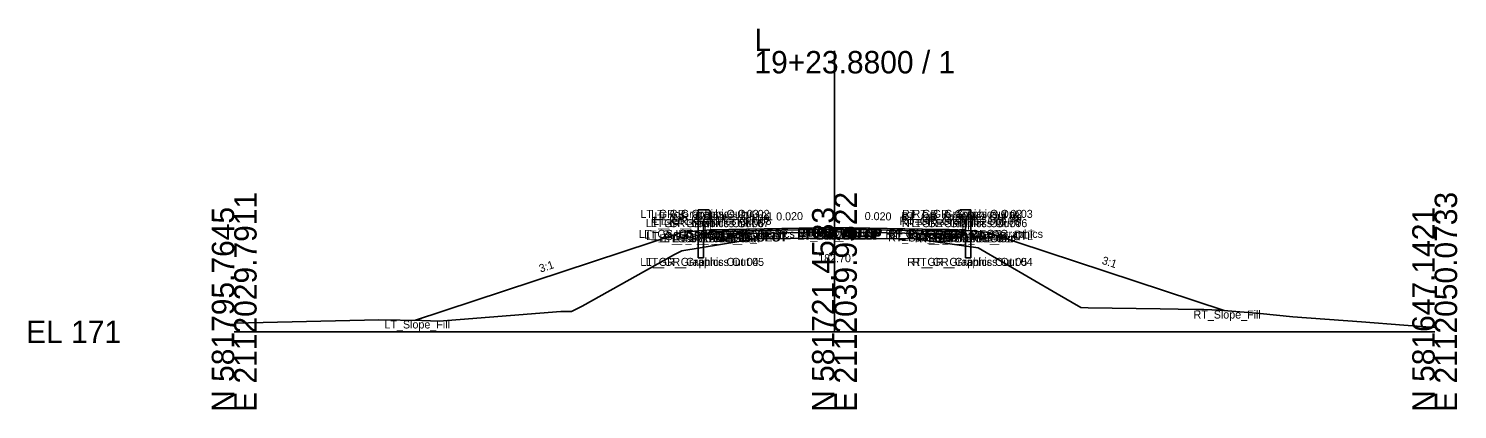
# Model space of a CAD drawing. Extents: x -26 to 3453, y -333 to 9539.
# Drawn here: x 3274.3 to 3452.8, y 990.3 to 1037.9 of the extents above; entities that cross this region are included whole.
import ezdxf

# ---------------------------------------------------------------- set-up
doc = ezdxf.new("R2010")
doc.units = 0
for name, color, linetype in [('Default', 7, 'Continuous'), ('Exist Cross Section Cell', 7, 'Continuous'), ('Exist XS Ground Line', 7, 'Continuous'), ('Prop CMT Guardrail Graphics', 7, 'Continuous'), ('Prop CMT Pvmt Course 1', 7, 'Continuous'), ('Prop CMT Pvmt Course 2', 7, 'Continuous'), ('Prop CMT Pvmt Course 3', 7, 'Continuous'), ('Prop CMT Pvmt Surface', 7, 'Continuous'), ('Prop CMT Pvmt Surface Shoulder', 7, 'Continuous'), ('Prop CMT Shld Paved Course 1', 7, 'Continuous'), ('Prop CMT Shld Paved Course 2', 7, 'Continuous'), ('Prop CMT Shld Paved Course 3', 7, 'Continuous'), ('Prop CMT Slope Grass', 7, 'Continuous'), ('Prop CMT Subgrade Earthwork', 7, 'Continuous'), ('Prop XS SE Text', 7, 'Continuous'), ('Prop XS Side Slope Text', 7, 'Continuous'), ('Scratch_Level_0', 7, 'Continuous')]:
    doc.layers.add(name, color=color, linetype=linetype)

msp = doc.modelspace()

# ---------------------------------------------------------------- linework, layer by layer
at = {"layer": 'Exist Cross Section Cell'}
for p, q in [((3375, 1000), (3375, 1035.09)), ((3300, 1000), (3375, 1000)), ((3375, 1000), (3450, 1000))]:
    msp.add_line(p, q, dxfattribs=at)
at = {"layer": 'Exist XS Ground Line'}
msp.add_lwpolyline([(3300, 1001.09), (3318.06, 1001.48), (3323.44, 1001.4), (3325.59, 1001.35), (3340.81, 1002.54), (3342.15, 1002.55), (3342.57, 1002.76), (3343.46, 1003.2), (3355.03, 1009.65), (3355.92, 1010.12), (3363.29, 1011.34), (3364.53, 1011.55), (3365.26, 1011.61), (3373.78, 1011.69), (3374.67, 1011.7), (3375, 1011.7), (3383.77, 1011.64), (3384.8, 1011.65), (3386.75, 1011.39), (3392.96, 1010.49), (3402.83, 1004.73), (3405.77, 1003.04), (3406.69, 1003.01), (3415.69, 1002.88), (3420.18, 1002.81), (3421.17, 1002.79), (3423.15, 1002.7), (3428.18, 1002.29), (3432.27, 1001.89), (3440.87, 1001.24), (3446.13, 1000.83), (3450, 1000.54)], dxfattribs=at)
at = {"layer": 'Prop CMT Guardrail Graphics'}
for points in [[(3357.97, 1009.24), (3357.97, 1015.24)], [(3357.97, 1015.24), (3359.3, 1015.24), (3359.57, 1014.95)], [(3359.57, 1014.37), (3359.3, 1014.08), (3358.64, 1014.08)], [(3358.64, 1014.08), (3358.64, 1009.24)], [(3359.57, 1014.95), (3359.3, 1014.66)], [(3359.3, 1014.66), (3359.57, 1014.37)], [(3392.03, 1015.24), (3390.7, 1015.24), (3390.43, 1014.95)], [(3390.43, 1014.95), (3390.7, 1014.66)], [(3390.7, 1014.66), (3390.43, 1014.37)], [(3390.43, 1014.37), (3390.7, 1014.08), (3391.36, 1014.08)], [(3391.36, 1014.08), (3391.36, 1009.24)], [(3392.03, 1009.24), (3392.03, 1015.24)], [(3358.64, 1009.24), (3357.97, 1009.24)], [(3391.36, 1009.24), (3392.03, 1009.24)]]:
    msp.add_lwpolyline(points, dxfattribs=at)
at = {"layer": 'Prop CMT Pvmt Course 1'}
for points in [[(3375, 1013.05), (3364, 1012.83)], [(3364, 1012.62), (3375, 1012.84)], [(3364, 1012.83), (3364, 1012.62)], [(3375, 1012.84), (3375, 1013.05)], [(3375, 1013.05), (3386, 1012.83)], [(3375, 1012.84), (3375, 1013.05)], [(3386, 1012.62), (3375, 1012.84)], [(3386, 1012.83), (3386, 1012.62)]]:
    msp.add_lwpolyline(points, dxfattribs=at)
msp.add_lwpolyline([(3375, 1012.84), (3375, 1012.93), (3375, 1012.93), (3375, 1012.84)], close=True, dxfattribs=at)
msp.add_lwpolyline([(3375, 1012.84), (3375, 1012.93), (3375, 1012.93), (3375, 1012.84)], close=True, dxfattribs=at)
at = {"layer": 'Prop CMT Pvmt Course 2'}
for points in [[(3375, 1012.84), (3364, 1012.62)], [(3364, 1012.62), (3364, 1012.29)], [(3364, 1012.29), (3375, 1012.51)], [(3375, 1012.51), (3375, 1012.84)], [(3375, 1012.51), (3375, 1012.84)], [(3375, 1012.84), (3386, 1012.62)], [(3386, 1012.29), (3375, 1012.51)], [(3386, 1012.62), (3386, 1012.29)]]:
    msp.add_lwpolyline(points, dxfattribs=at)
at = {"layer": 'Prop CMT Pvmt Course 3'}
for points in [[(3375, 1012.51), (3364, 1012.29)], [(3364, 1012.29), (3375, 1012.51)], [(3364, 1012.29), (3364, 1012.29)], [(3375, 1012.51), (3375, 1012.51)], [(3375, 1012.51), (3386, 1012.29)], [(3386, 1012.29), (3375, 1012.51)], [(3375, 1012.51), (3375, 1012.51)], [(3386, 1012.29), (3386, 1012.29)]]:
    msp.add_lwpolyline(points, dxfattribs=at)
at = {"layer": 'Prop CMT Pvmt Surface'}
for points in [[(3375, 1013.05), (3364, 1012.83)], [(3375, 1013.05), (3386, 1012.83)]]:
    msp.add_lwpolyline(points, dxfattribs=at)
at = {"layer": 'Prop CMT Pvmt Surface Shoulder'}
for points in [[(3364, 1012.83), (3359.58, 1012.74)], [(3386, 1012.83), (3390.42, 1012.74)]]:
    msp.add_lwpolyline(points, dxfattribs=at)
at = {"layer": 'Prop CMT Shld Paved Course 1'}
for points in [[(3364, 1012.83), (3359.58, 1012.74), (3359.37, 1012.53)], [(3359.37, 1012.53), (3364, 1012.62)], [(3364, 1012.62), (3364, 1012.83)], [(3386, 1012.83), (3390.42, 1012.74), (3390.63, 1012.53)], [(3386, 1012.62), (3386, 1012.83)], [(3390.63, 1012.53), (3386, 1012.62)]]:
    msp.add_lwpolyline(points, dxfattribs=at)
at = {"layer": 'Prop CMT Shld Paved Course 2'}
for points in [[(3364, 1012.62), (3359.37, 1012.53), (3359.03, 1012.19)], [(3359.03, 1012.19), (3364, 1012.29)], [(3364, 1012.29), (3364, 1012.62)], [(3386, 1012.62), (3390.63, 1012.53), (3390.97, 1012.19)], [(3386, 1012.29), (3386, 1012.62)], [(3390.97, 1012.19), (3386, 1012.29)]]:
    msp.add_lwpolyline(points, dxfattribs=at)
at = {"layer": 'Prop CMT Shld Paved Course 3'}
for points in [[(3364, 1012.29), (3359.03, 1012.19)], [(3359.03, 1012.19), (3364, 1012.29)], [(3364, 1012.29), (3364, 1012.29)], [(3386, 1012.29), (3390.97, 1012.19)], [(3390.97, 1012.19), (3386, 1012.29)], [(3386, 1012.29), (3386, 1012.29)], [(3359.03, 1012.19), (3359.03, 1012.19), (3359.03, 1012.19)], [(3390.97, 1012.19), (3390.97, 1012.19), (3390.97, 1012.19)]]:
    msp.add_lwpolyline(points, dxfattribs=at)
at = {"layer": 'Prop CMT Slope Grass'}
for points in [[(3356, 1012.46), (3322.54, 1001.42)], [(3359.57, 1012.74), (3356, 1012.46)], [(3359.58, 1012.74), (3359.57, 1012.74)], [(3390.42, 1012.74), (3390.43, 1012.74)], [(3390.43, 1012.74), (3394, 1012.46)], [(3394, 1012.46), (3423.7, 1002.66)]]:
    msp.add_lwpolyline(points, dxfattribs=at)
at = {"layer": 'Prop CMT Subgrade Earthwork'}
for points in [[(3359.03, 1012.19), (3358.56, 1012.66)], [(3364, 1012.29), (3359.03, 1012.19)], [(3375, 1012.51), (3364, 1012.29)], [(3375, 1012.51), (3386, 1012.29)], [(3386, 1012.29), (3390.97, 1012.19)], [(3390.97, 1012.19), (3391.44, 1012.66)]]:
    msp.add_lwpolyline(points, dxfattribs=at)

# ---------------------------------------------------------------- texts
at = {"layer": 'Default'}
msp.add_text('-', height=0.0001, dxfattribs=at).set_placement((3300, 1000))
at = {"layer": 'Exist Cross Section Cell'}
for s, p in [('L', (3365, 1035.09)), ('19+23.8800 / 1', (3365, 1032.29)), ('EL 171', (3274, 998.6))]:
    msp.add_text(s, height=2.8, dxfattribs=at).set_placement(p)
for s, p in [('E 2112029.7911', (3302.8, 990)), ('E 2112039.9322', (3377.8, 990)), ('E 2112050.0733', (3452.8, 990)), ('N 581795.7645', (3300, 990)), ('N 581721.4533', (3375, 990)), ('N 581647.1421', (3450, 990))]:
    msp.add_text(s, height=2.8, rotation=90, dxfattribs=at).set_placement(p)
at = {"layer": 'Exist XS Ground Line'}
msp.add_text('182.70', height=1, dxfattribs=at).set_placement((3372.97, 1008.7))
at = {"layer": 'Prop XS SE Text'}
for rotation, p in [(1.1458, (3367.73, 1013.91)), (358.8542, (3378.77, 1013.98))]:
    msp.add_text('0.020', height=1, rotation=rotation, dxfattribs=at).set_placement(p)
at = {"layer": 'Prop XS Side Slope Text'}
for rotation, p in [(18.2629, (3338.28, 1007.4)), (341.7371, (3408.33, 1008.52))]:
    msp.add_text('3:1', height=1, rotation=rotation, dxfattribs=at).set_placement(p)
at = {"layer": 'Scratch_Level_0'}
for s, p in [('LT_GR_Graphics Out 03', (3350.75, 1014.24)), ('LT_GR_Graphics Out 06', (3351.41, 1013.08)), ('LT_GR_Graphics Out 07', (3352.06, 1013.08)), ('LT_GR_Graphics Out 09', (3352.08, 1013.66)), ('LT_GR_Graphics Out 02', (3352.1, 1014.24)), ('LT_GR_Graphics Out 08', (3352.34, 1013.37)), ('LT_GR_Graphics Out 01', (3352.52, 1013.95)), ('RT_GR_Graphics Out 08', (3383.14, 1013.37)), ('RT_GR_Graphics Out 01', (3383.31, 1013.95)), ('RT_GR_Graphics Out 07', (3383.4, 1013.08)), ('RT_GR_Graphics Out 09', (3383.41, 1013.66)), ('RT_GR_Graphics Out 02', (3383.44, 1014.24)), ('RT_GR_Graphics Out 06', (3384.08, 1013.08)), ('RT_GR_Graphics Out 03', (3384.76, 1014.24)), ('LT_GS_OS_GR_Face_Graphics', (3350.57, 1011.74)), ('LT_Sub_Trench_Out_DLT', (3351.21, 1011.66)), ('LT_GS_OS_CTL', (3351.46, 1011.46)), ('LT_PS2_OEOP', (3355.16, 1011.53)), ('LT_PS1_OEOP', (3355.49, 1011.74)), ('LT_PV2_OEOT', (3359.75, 1011.62)), ('LT_PV3_OEOT', (3359.75, 1011.29)), ('LT_Sub_OEOT', (3359.77, 1011.29)), ('LT_PV1_OEOT', (3359.87, 1011.83)), ('RT_PV2_OEEOP', (3370.33, 1011.84)), ('RT_PV3_OEEOP', (3370.33, 1011.51)), ('RT_Sub_OEEOP', (3370.36, 1011.51)), ('LT_PV2_OEEOP', (3370.39, 1011.84)), ('LT_PV3_OEEOP', (3370.39, 1011.51)), ('LT_Sub_OEEOP', (3370.42, 1011.51)), ('RT_PV1_OEEOP', (3370.45, 1011.93)), ('LT_PV1_OEEOP', (3370.51, 1011.93)), ('RT_PV2_IEEOP', (3370.71, 1011.84)), ('LT_PV2_IEEOP', (3370.77, 1011.84)), ('RT_PV1_IEEOP', (3370.83, 1011.93)), ('LT_PV1_IEEOP', (3370.89, 1011.93)), ('PV2_PGL', (3372.35, 1011.84)), ('PV1_PGL', (3372.47, 1012.05)), ('RT_GS_OS_GR_Face_Graphics', (3381.36, 1011.74)), ('RT_PV2_OEOT', (3381.69, 1011.62)), ('RT_PV3_OEOT', (3381.69, 1011.29)), ('RT_Sub_OEOT', (3381.71, 1011.29)), ('RT_PV1_OEOT', (3381.81, 1011.83)), ('RT_Sub_Trench_Out_DLT', (3384.03, 1011.66)), ('RT_PS1_OEOP', (3386.26, 1011.74)), ('RT_PS2_OEOP', (3386.36, 1011.53)), ('RT_GS_OS_CTL', (3389.4, 1011.46)), ('LT_Sub_Trench_Out', (3353.14, 1011.19)), ('LT_PS3_Shelf_Out', (3353.69, 1011.19)), ('LT_PS3_OEOP', (3354.82, 1011.19)), ('RT_Sub_Trench_Out', (3385.02, 1011.19)), ('RT_PS3_Shelf_Out', (3385.57, 1011.19)), ('RT_PS3_OEOP', (3386.7, 1011.19)), ('LT_GR_Graphics Out 04', (3350.74, 1008.24)), ('LT_GR_Graphics Out 05', (3351.41, 1008.24)), ('RT_GR_Graphics Out 05', (3384.08, 1008.24)), ('RT_GR_Graphics Out 04', (3384.74, 1008.24)), ('RT_Slope_Fill', (3419.87, 1001.66)), ('LT_Slope_Fill', (3318.78, 1000.42))]:
    msp.add_text(s, height=1, dxfattribs=at).set_placement(p)

doc.saveas('drawing.dxf')
